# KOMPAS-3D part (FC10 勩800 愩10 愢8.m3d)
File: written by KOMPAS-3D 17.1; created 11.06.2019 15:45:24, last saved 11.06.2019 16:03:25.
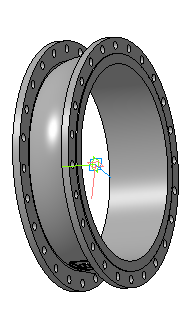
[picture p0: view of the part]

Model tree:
1. Операция без истории:2  (labels: Сталь 20  ГОСТ 1050-2013)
